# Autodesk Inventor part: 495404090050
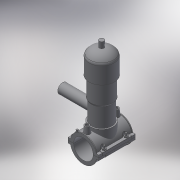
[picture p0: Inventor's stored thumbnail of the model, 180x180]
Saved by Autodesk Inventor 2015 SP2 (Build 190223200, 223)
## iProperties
Created: 2017-07
Part Number: 495404090050
Material: Generic
Description: PLASSON TAPPING VALVE 90-50
Document SubType Name: Modeling
Designer: KIM
Density: 1 g/cm^3
Appearance: Default
Author: KIM
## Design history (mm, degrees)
derived "495404-4954S4.ipt"
feature "Solid1::495404-4954S4.ipt"
feature "Solid2::495404-4954S4.ipt"
tag "TaggingFeature1"
body "Solid1"
body "Solid2"
other parameters: "d2" = 126, "d3" = 22.5, "d4" = 118, "d5" = 0, "d6" = 0.1, "d8" = 0, "d19" = 6, "d20" = 6, "d21" = 70.8, "d23" = 0, "d24" = 35.4, "d26" = 0, "d27" = 3, "d28" = 3, "d29" = 3, "d31" = 6, "d32" = 0, "d33" = 0, "d34" = 0.6, "d40" = 60.84, "d47" = 109.5, "d70" = 15, "d72" = 0, "d73" = 6, "d75" = 5, "d76" = 0, "d77" = 4.5, "d78" = 75, "d79" = 15, "d80" = 47.2, "d82" = 5 deg, "d84" = 4, "d85" = 14, "d86" = 0, "d87" = 3, "d88" = 0, "d89" = 1, "d90" = 1, "d91" = 94.4, "d92" = 0, "d93" = 0.5, "d94" = 47.36842, "d96" = 120.51, "d97" = 2.36, "d98" = 0, "d120" = 140 deg, "d121" = 24.228, "d122" = 20 deg, "d123" = 234, "d124" = 70.2, "d126" = 0, "d143" = 92.7, "d145" = 20.76923, "d149" = 1.35, "d150" = 22.84615, "d153" = 118, "d154" = 0, "d156" = 58.5, "d157" = 160 deg, "d159" = 5.4, "d161" = 1.35, "d162" = 70.8, "d163" = 0, "d164" = 45, "d167" = 9, "d168" = 57.07317, "d170" = 3, "d172" = 0, "d173" = 1, "d175" = 45, "d176" = 20 deg, "d177" = 6.3, "d178" = 27, "d180" = 0, "d183" = 10.8, "d184" = 5.04, "d185" = 38.35, "d186" = 38.35, "d187" = 58.5, "d188" = 8.1, "d189" = 6.3, "d190" = 0, "d191" = 87.75, "d193" = 6.8, "d194" = 2.95, "d195" = 90 deg, "d197" = 0, "d199" = 0, "d205" = 14.64, "d206" = 81.33333, "d207" = 244, "d208" = 224.48, "d209" = 207.4, "d210" = 200.08, "d211" = 146.4, "d212" = 85.4, "d213" = 65.88, "d214" = 73.2, "d216" = 19.52, "d217" = 70.76, "d218" = 80.52, "d222" = 0, "d223" = 117, "d224" = 152, "d225" = 51, "d229" = 152, "d230" = 0, "B_" = 126, "H_" = 152, "L_" = 118, "d_t" = 6, "H_1" = 51, "H_2" = 244, "d148" = 1.35, "d160" = 1.35, "d169" = 3, "d192" = 6.8
